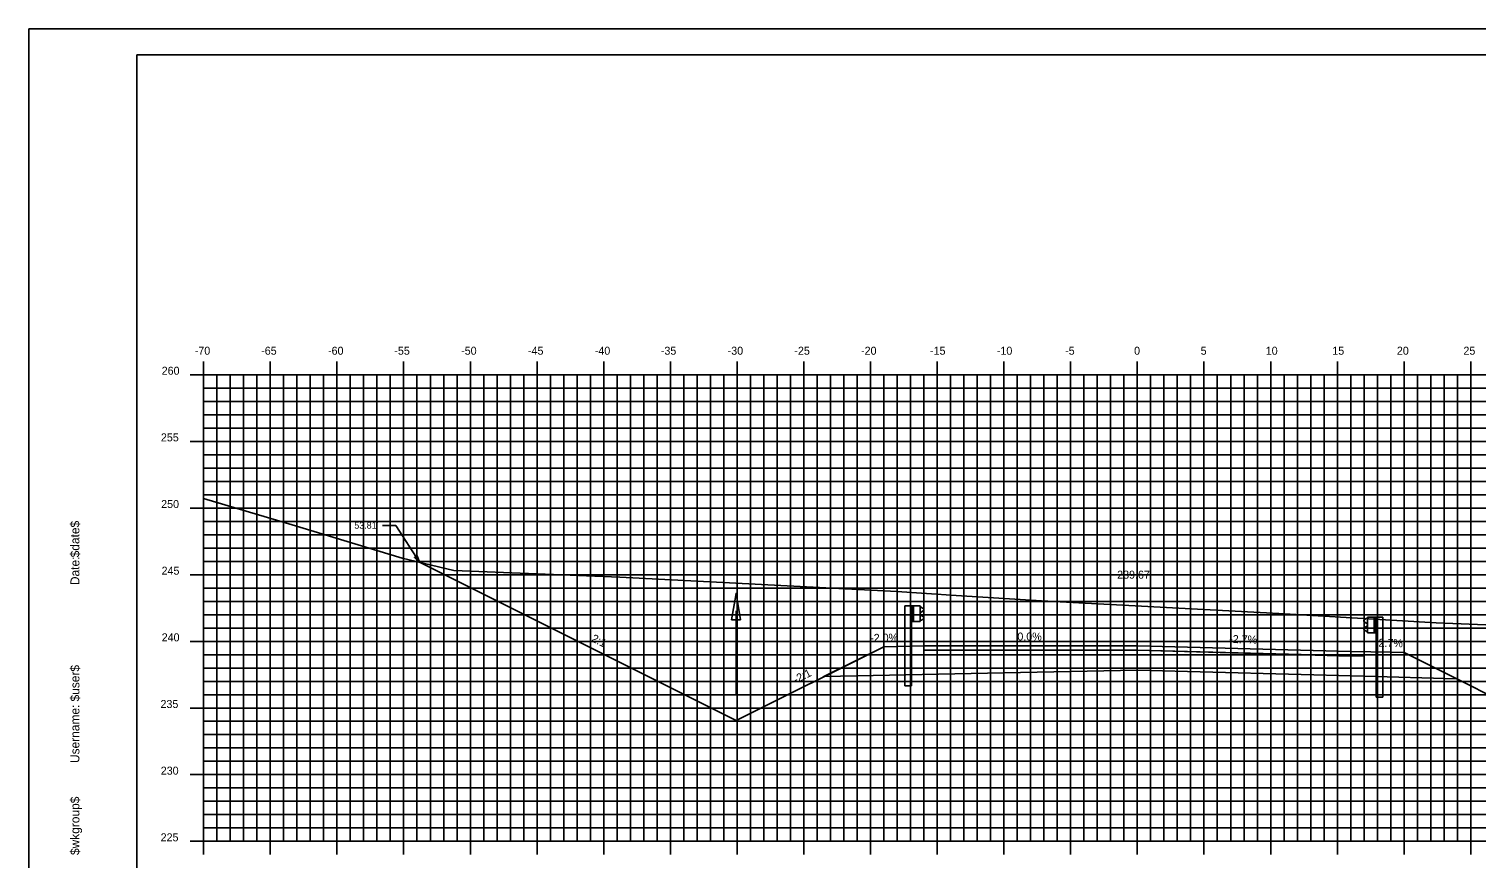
# Model space of a CAD drawing. Extents: x 1160718 to 1173142, y 616002 to 617630.
# Drawn here: x 1168770.5 to 1168879, y 616661.7 to 616723.9 of the extents above; entities that cross this region are included whole.
import ezdxf

# ---------------------------------------------------------------- set-up
doc = ezdxf.new("R2010")
doc.units = 0
for name, color, linetype in [('ANNOTATION', 7, 'Continuous'), ('BORDER', 7, 'Continuous'), ('D_Drainage_Ditch_Line', 7, 'Continuous'), ('D_Guardrail_Beam_Lt', 7, 'Continuous'), ('D_Guardrail_Beam_Rt', 7, 'Continuous'), ('D_Roadway_Centerline', 7, 'Continuous'), ('D_Roadway_Centerline_Text', 7, 'Continuous'), ('D_Roadway_Edge_Shoulder', 7, 'Continuous'), ('D_Roadway_Edge_TW', 7, 'Continuous'), ('D_Roadway_Pavement', 7, 'Continuous'), ('D_Roadway_SlopeLines', 7, 'Continuous'), ('D_Roadway_SubGrade', 7, 'Continuous'), ('H_V ANNOTATION', 7, 'Continuous'), ('MAJOR', 7, 'Continuous'), ('MINOR', 7, 'Continuous'), ('PLOT BOUNDARY', 7, 'Continuous'), ('S_Roadway_Centerline', 7, 'Continuous'), ('SHADING', 7, 'Continuous')]:
    doc.layers.add(name, color=color, linetype=linetype)

msp = doc.modelspace()

# ---------------------------------------------------------------- linework, layer by layer
at = {"layer": 'ANNOTATION'}
for p in [(1168797.02, 616686.63), (1168799.8, 616683.86)]:
    msp.add_line(p, (1168798.02, 616686.63), dxfattribs=at)
msp.add_lwpolyline([(1168799.63, 616684.35), (1168799.8, 616683.86), (1168799.42, 616684.21)], close=True, dxfattribs=at)
at = {"layer": 'BORDER'}
for p, q in [((1168938.61, 616721.93), (1168778.61, 616721.93)), ((1168778.61, 616721.93), (1168778.61, 616616.93))]:
    msp.add_line(p, q, dxfattribs=at)
at = {"layer": 'D_Drainage_Ditch_Line'}
msp.add_line((1168823.53, 616680.21), (1168823.53, 616673.96), dxfattribs=at)
msp.add_lwpolyline([(1168823.86, 616679.55), (1168823.2, 616679.55), (1168823.53, 616681.52)], close=True, dxfattribs=at)
at = {"layer": 'D_Guardrail_Beam_Lt'}
for p, q in [((1168836.18, 616680.59), (1168836.18, 616674.59)), ((1168836.65, 616680.59), (1168836.18, 616680.59)), ((1168837.34, 616680.59), (1168836.65, 616680.59)), ((1168836.65, 616680.59), (1168836.65, 616679.42)), ((1168836.72, 616680.59), (1168836.72, 616679.42)), ((1168836.82, 616680.59), (1168836.82, 616679.42)), ((1168837.34, 616679.42), (1168837.34, 616680.59)), ((1168837.34, 616680.5), (1168837.41, 616680.49)), ((1168837.57, 616680.24), (1168837.38, 616680.1)), ((1168837.43, 616680.48), (1168837.57, 616680.38)), ((1168836.65, 616679.42), (1168837.34, 616679.42)), ((1168836.67, 616674.59), (1168836.67, 616679.42)), ((1168837.34, 616680.04), (1168837.34, 616679.97)), ((1168837.41, 616679.52), (1168837.34, 616679.5)), ((1168837.38, 616679.9), (1168837.57, 616679.77)), ((1168837.57, 616679.62), (1168837.43, 616679.52)), ((1168836.67, 616674.59), (1168836.18, 616674.59))]:
    msp.add_line(p, q, dxfattribs=at)
for centre, major_axis, start_param, end_param in [((1168837.42, 616680.04), (-0.0789, 0), 5.323254, 6.283185), ((1168837.41, 616680.45), (0.0417, 0), 0.959931, 1.376053), ((1168837.52, 616680.31), (0.0877, 0), 5.323254, 7.243116), ((1168837.42, 616679.97), (-0.0789, 0), 6.283185, 7.243116), ((1168837.41, 616679.56), (0.0417, 0), 4.907132, 5.323254), ((1168837.52, 616679.7), (0.0877, 0), 5.323254, 7.243116)]:
    msp.add_ellipse(centre, major_axis=major_axis, ratio=0.995501, start_param=start_param, end_param=end_param, dxfattribs=at)
at = {"layer": 'D_Guardrail_Beam_Rt'}
for p, q in [((1168870.77, 616679.65), (1168870.63, 616679.55)), ((1168870.63, 616679.4), (1168870.82, 616679.27)), ((1168870.82, 616679.07), (1168870.63, 616678.93)), ((1168870.86, 616679.67), (1168870.79, 616679.65)), ((1168870.86, 616679.75), (1168871.55, 616679.75)), ((1168870.86, 616678.58), (1168870.86, 616679.75)), ((1168870.86, 616679.2), (1168870.86, 616679.13)), ((1168871.38, 616679.75), (1168871.38, 616678.58)), ((1168871.49, 616679.75), (1168871.49, 616678.58)), ((1168871.55, 616679.75), (1168872.02, 616679.75)), ((1168871.55, 616679.75), (1168871.55, 616678.58)), ((1168872.02, 616679.75), (1168872.02, 616673.75)), ((1168870.63, 616678.79), (1168870.77, 616678.69)), ((1168870.79, 616678.68), (1168870.86, 616678.67)), ((1168871.55, 616678.58), (1168870.86, 616678.58)), ((1168871.53, 616673.75), (1168871.53, 616678.58)), ((1168871.53, 616673.75), (1168872.02, 616673.75))]:
    msp.add_line(p, q, dxfattribs=at)
for centre, major_axis, start_param, end_param in [((1168870.68, 616679.47), (-0.0877, 0), 5.323254, 7.243116), ((1168870.8, 616679.61), (-0.0417, 0), 4.907132, 5.323254), ((1168870.78, 616679.2), (0.0789, 0), 0, 0.959931), ((1168870.78, 616679.13), (0.0789, 0), 5.323254, 6.283185), ((1168870.68, 616678.86), (-0.0877, 0), 5.323254, 7.243116), ((1168870.8, 616678.72), (-0.0417, 0), 0.959931, 1.376053)]:
    msp.add_ellipse(centre, major_axis=major_axis, ratio=0.995501, start_param=start_param, end_param=end_param, dxfattribs=at)
at = {"layer": 'D_Roadway_Edge_Shoulder'}
msp.add_lwpolyline([(1168837.61, 616677.59), (1168837.61, 616677.26)], dxfattribs=at)
at = {"layer": 'D_Roadway_Edge_TW'}
for p, q in [((1168837.61, 616677.26), (1168837.61, 616677.59)), ((1168837.61, 616677.59), (1168853.61, 616677.59)), ((1168853.61, 616677.26), (1168837.61, 616677.26)), ((1168853.61, 616677.59), (1168869.61, 616677.17)), ((1168869.61, 616676.83), (1168853.61, 616677.26))]:
    msp.add_line(p, q, dxfattribs=at)
at = {"layer": 'D_Roadway_Pavement'}
msp.add_lwpolyline([(1168837.61, 616677.26), (1168837.61, 616677.26), (1168853.61, 616677.26), (1168869.61, 616676.83), (1168869.61, 616676.83), (1168853.61, 616677.26)], close=True, dxfattribs=at)
for points in [[(1168837.61, 616677.26), (1168837.61, 616677.26)], [(1168837.61, 616677.26), (1168837.61, 616677.26)], [(1168869.61, 616676.83), (1168869.61, 616676.83)], [(1168869.61, 616676.83), (1168869.61, 616676.83)]]:
    msp.add_lwpolyline(points, dxfattribs=at)
at = {"layer": 'D_Roadway_SlopeLines'}
for points in [[(1168823.53, 616671.99), (1168799.8, 616683.86)], [(1168834.61, 616677.53), (1168823.53, 616671.99)], [(1168873.61, 616677.09), (1168884.69, 616671.55)]]:
    msp.add_lwpolyline(points, dxfattribs=at)
at = {"layer": 'D_Roadway_SubGrade'}
for p, q in [((1168834.61, 616677.53), (1168830.06, 616675.26)), ((1168837.61, 616677.59), (1168834.61, 616677.53)), ((1168837.61, 616675.44), (1168837.61, 616677.59)), ((1168837.61, 616675.76), (1168837.61, 616677.26)), ((1168837.61, 616677.26), (1168853.61, 616677.26)), ((1168853.61, 616677.26), (1168870.61, 616676.81)), ((1168869.61, 616677.17), (1168872.61, 616677.11)), ((1168870.61, 616675.31), (1168870.61, 616677.15))]:
    msp.add_line(p, q, dxfattribs=at)
msp.add_lwpolyline([(1168869.61, 616677.17), (1168872.61, 616677.11), (1168873.61, 616677.09)], dxfattribs=at)
at = {"layer": 'MAJOR'}
for p, q in [((1168783.61, 616698.93), (1168783.61, 616697.93)), ((1168788.61, 616698.93), (1168788.61, 616697.93)), ((1168793.61, 616698.93), (1168793.61, 616697.93)), ((1168798.61, 616698.93), (1168798.61, 616697.93)), ((1168803.61, 616698.93), (1168803.61, 616697.93)), ((1168808.61, 616698.93), (1168808.61, 616697.93)), ((1168813.61, 616698.93), (1168813.61, 616697.93)), ((1168818.61, 616698.93), (1168818.61, 616697.93)), ((1168823.61, 616698.93), (1168823.61, 616697.93)), ((1168828.61, 616698.93), (1168828.61, 616697.93)), ((1168833.61, 616698.93), (1168833.61, 616697.93)), ((1168838.61, 616698.93), (1168838.61, 616697.93)), ((1168843.61, 616698.93), (1168843.61, 616697.93)), ((1168848.61, 616698.93), (1168848.61, 616697.93)), ((1168853.61, 616698.93), (1168853.61, 616697.93)), ((1168858.61, 616698.93), (1168858.61, 616697.93)), ((1168863.61, 616698.93), (1168863.61, 616697.93)), ((1168868.61, 616698.93), (1168868.61, 616697.93)), ((1168873.61, 616698.93), (1168873.61, 616697.93)), ((1168878.61, 616698.93), (1168878.61, 616697.93)), ((1168782.61, 616697.93), (1168783.61, 616697.93)), ((1168783.61, 616697.93), (1168923.61, 616697.93)), ((1168783.61, 616662.93), (1168783.61, 616697.93)), ((1168783.61, 616662.93), (1168783.61, 616697.93)), ((1168783.61, 616697.93), (1168923.61, 616697.93)), ((1168788.61, 616662.93), (1168788.61, 616697.93)), ((1168793.61, 616662.93), (1168793.61, 616697.93)), ((1168798.61, 616662.93), (1168798.61, 616697.93)), ((1168803.61, 616662.93), (1168803.61, 616697.93)), ((1168808.61, 616662.93), (1168808.61, 616697.93)), ((1168813.61, 616662.93), (1168813.61, 616697.93)), ((1168818.61, 616662.93), (1168818.61, 616697.93)), ((1168823.61, 616662.93), (1168823.61, 616697.93)), ((1168828.61, 616662.93), (1168828.61, 616697.93)), ((1168833.61, 616662.93), (1168833.61, 616697.93)), ((1168838.61, 616662.93), (1168838.61, 616697.93)), ((1168843.61, 616662.93), (1168843.61, 616697.93)), ((1168848.61, 616662.93), (1168848.61, 616697.93)), ((1168853.61, 616662.93), (1168853.61, 616697.93)), ((1168858.61, 616662.93), (1168858.61, 616697.93)), ((1168863.61, 616662.93), (1168863.61, 616697.93)), ((1168868.61, 616662.93), (1168868.61, 616697.93)), ((1168873.61, 616662.93), (1168873.61, 616697.93)), ((1168878.61, 616662.93), (1168878.61, 616697.93)), ((1168782.61, 616692.93), (1168783.61, 616692.93)), ((1168783.61, 616692.93), (1168923.61, 616692.93)), ((1168782.61, 616687.93), (1168783.61, 616687.93)), ((1168783.61, 616687.93), (1168923.61, 616687.93)), ((1168782.61, 616682.93), (1168783.61, 616682.93)), ((1168783.61, 616682.93), (1168923.61, 616682.93)), ((1168782.61, 616677.93), (1168783.61, 616677.93)), ((1168783.61, 616677.93), (1168923.61, 616677.93)), ((1168782.61, 616672.93), (1168783.61, 616672.93)), ((1168783.61, 616672.93), (1168923.61, 616672.93)), ((1168782.61, 616667.93), (1168783.61, 616667.93)), ((1168783.61, 616667.93), (1168923.61, 616667.93)), ((1168782.61, 616662.93), (1168783.61, 616662.93)), ((1168783.61, 616662.93), (1168923.61, 616662.93)), ((1168783.61, 616662.93), (1168923.61, 616662.93)), ((1168783.61, 616661.93), (1168783.61, 616662.93)), ((1168788.61, 616661.93), (1168788.61, 616662.93)), ((1168793.61, 616661.93), (1168793.61, 616662.93)), ((1168798.61, 616661.93), (1168798.61, 616662.93)), ((1168803.61, 616661.93), (1168803.61, 616662.93)), ((1168808.61, 616661.93), (1168808.61, 616662.93)), ((1168813.61, 616661.93), (1168813.61, 616662.93)), ((1168818.61, 616661.93), (1168818.61, 616662.93)), ((1168823.61, 616661.93), (1168823.61, 616662.93)), ((1168828.61, 616661.93), (1168828.61, 616662.93)), ((1168833.61, 616661.93), (1168833.61, 616662.93)), ((1168838.61, 616661.93), (1168838.61, 616662.93)), ((1168843.61, 616661.93), (1168843.61, 616662.93)), ((1168848.61, 616661.93), (1168848.61, 616662.93)), ((1168853.61, 616661.93), (1168853.61, 616662.93)), ((1168858.61, 616661.93), (1168858.61, 616662.93)), ((1168863.61, 616661.93), (1168863.61, 616662.93)), ((1168868.61, 616661.93), (1168868.61, 616662.93)), ((1168873.61, 616661.93), (1168873.61, 616662.93)), ((1168878.61, 616661.93), (1168878.61, 616662.93))]:
    msp.add_line(p, q, dxfattribs=at)
at = {"layer": 'MINOR'}
for p, q in [((1168784.61, 616662.93), (1168784.61, 616697.93)), ((1168785.61, 616662.93), (1168785.61, 616697.93)), ((1168786.61, 616662.93), (1168786.61, 616697.93)), ((1168787.61, 616662.93), (1168787.61, 616697.93)), ((1168789.61, 616662.93), (1168789.61, 616697.93)), ((1168790.61, 616662.93), (1168790.61, 616697.93)), ((1168791.61, 616662.93), (1168791.61, 616697.93)), ((1168792.61, 616662.93), (1168792.61, 616697.93)), ((1168794.61, 616662.93), (1168794.61, 616697.93)), ((1168795.61, 616662.93), (1168795.61, 616697.93)), ((1168796.61, 616662.93), (1168796.61, 616697.93)), ((1168797.61, 616662.93), (1168797.61, 616697.93)), ((1168799.61, 616662.93), (1168799.61, 616697.93)), ((1168800.61, 616662.93), (1168800.61, 616697.93)), ((1168801.61, 616662.93), (1168801.61, 616697.93)), ((1168802.61, 616662.93), (1168802.61, 616697.93)), ((1168804.61, 616662.93), (1168804.61, 616697.93)), ((1168805.61, 616662.93), (1168805.61, 616697.93)), ((1168806.61, 616662.93), (1168806.61, 616697.93)), ((1168807.61, 616662.93), (1168807.61, 616697.93)), ((1168809.61, 616662.93), (1168809.61, 616697.93)), ((1168810.61, 616662.93), (1168810.61, 616697.93)), ((1168811.61, 616662.93), (1168811.61, 616697.93)), ((1168812.61, 616662.93), (1168812.61, 616697.93)), ((1168814.61, 616662.93), (1168814.61, 616697.93)), ((1168815.61, 616662.93), (1168815.61, 616697.93)), ((1168816.61, 616662.93), (1168816.61, 616697.93)), ((1168817.61, 616662.93), (1168817.61, 616697.93)), ((1168819.61, 616662.93), (1168819.61, 616697.93)), ((1168820.61, 616662.93), (1168820.61, 616697.93)), ((1168821.61, 616662.93), (1168821.61, 616697.93)), ((1168822.61, 616662.93), (1168822.61, 616697.93)), ((1168824.61, 616662.93), (1168824.61, 616697.93)), ((1168825.61, 616662.93), (1168825.61, 616697.93)), ((1168826.61, 616662.93), (1168826.61, 616697.93)), ((1168827.61, 616662.93), (1168827.61, 616697.93)), ((1168829.61, 616662.93), (1168829.61, 616697.93)), ((1168830.61, 616662.93), (1168830.61, 616697.93)), ((1168831.61, 616662.93), (1168831.61, 616697.93)), ((1168832.61, 616662.93), (1168832.61, 616697.93)), ((1168834.61, 616662.93), (1168834.61, 616697.93)), ((1168835.61, 616662.93), (1168835.61, 616697.93)), ((1168836.61, 616662.93), (1168836.61, 616697.93)), ((1168837.61, 616662.93), (1168837.61, 616697.93)), ((1168839.61, 616662.93), (1168839.61, 616697.93)), ((1168840.61, 616662.93), (1168840.61, 616697.93)), ((1168841.61, 616662.93), (1168841.61, 616697.93)), ((1168842.61, 616662.93), (1168842.61, 616697.93)), ((1168844.61, 616662.93), (1168844.61, 616697.93)), ((1168845.61, 616662.93), (1168845.61, 616697.93)), ((1168846.61, 616662.93), (1168846.61, 616697.93)), ((1168847.61, 616662.93), (1168847.61, 616697.93)), ((1168849.61, 616662.93), (1168849.61, 616697.93)), ((1168850.61, 616662.93), (1168850.61, 616697.93)), ((1168851.61, 616662.93), (1168851.61, 616697.93)), ((1168852.61, 616662.93), (1168852.61, 616697.93)), ((1168854.61, 616662.93), (1168854.61, 616697.93)), ((1168855.61, 616662.93), (1168855.61, 616697.93)), ((1168856.61, 616662.93), (1168856.61, 616697.93)), ((1168857.61, 616662.93), (1168857.61, 616697.93)), ((1168859.61, 616662.93), (1168859.61, 616697.93)), ((1168860.61, 616662.93), (1168860.61, 616697.93)), ((1168861.61, 616662.93), (1168861.61, 616697.93)), ((1168862.61, 616662.93), (1168862.61, 616697.93)), ((1168864.61, 616662.93), (1168864.61, 616697.93)), ((1168865.61, 616662.93), (1168865.61, 616697.93)), ((1168866.61, 616662.93), (1168866.61, 616697.93)), ((1168867.61, 616662.93), (1168867.61, 616697.93)), ((1168869.61, 616662.93), (1168869.61, 616697.93)), ((1168870.61, 616662.93), (1168870.61, 616697.93)), ((1168871.61, 616662.93), (1168871.61, 616697.93)), ((1168872.61, 616662.93), (1168872.61, 616697.93)), ((1168874.61, 616662.93), (1168874.61, 616697.93)), ((1168875.61, 616662.93), (1168875.61, 616697.93)), ((1168876.61, 616662.93), (1168876.61, 616697.93)), ((1168877.61, 616662.93), (1168877.61, 616697.93)), ((1168783.61, 616696.93), (1168923.61, 616696.93)), ((1168783.61, 616696.93), (1168784.61, 616696.93)), ((1168783.61, 616695.93), (1168923.61, 616695.93)), ((1168783.61, 616695.93), (1168784.61, 616695.93)), ((1168783.61, 616694.93), (1168923.61, 616694.93)), ((1168783.61, 616694.93), (1168784.61, 616694.93)), ((1168783.61, 616693.93), (1168923.61, 616693.93)), ((1168783.61, 616693.93), (1168784.61, 616693.93)), ((1168783.61, 616691.93), (1168923.61, 616691.93)), ((1168783.61, 616691.93), (1168784.61, 616691.93)), ((1168783.61, 616690.93), (1168923.61, 616690.93)), ((1168783.61, 616690.93), (1168784.61, 616690.93)), ((1168783.61, 616689.93), (1168923.61, 616689.93)), ((1168783.61, 616689.93), (1168784.61, 616689.93)), ((1168783.61, 616688.93), (1168923.61, 616688.93)), ((1168783.61, 616688.93), (1168784.61, 616688.93)), ((1168783.61, 616686.93), (1168923.61, 616686.93)), ((1168783.61, 616686.93), (1168784.61, 616686.93)), ((1168783.61, 616685.93), (1168923.61, 616685.93)), ((1168783.61, 616685.93), (1168784.61, 616685.93)), ((1168783.61, 616684.93), (1168923.61, 616684.93)), ((1168783.61, 616684.93), (1168784.61, 616684.93)), ((1168783.61, 616683.93), (1168923.61, 616683.93)), ((1168783.61, 616683.93), (1168784.61, 616683.93)), ((1168783.61, 616681.93), (1168923.61, 616681.93)), ((1168783.61, 616681.93), (1168784.61, 616681.93)), ((1168783.61, 616680.93), (1168923.61, 616680.93)), ((1168783.61, 616680.93), (1168784.61, 616680.93)), ((1168783.61, 616679.93), (1168923.61, 616679.93)), ((1168783.61, 616679.93), (1168784.61, 616679.93)), ((1168783.61, 616678.93), (1168923.61, 616678.93)), ((1168783.61, 616678.93), (1168784.61, 616678.93)), ((1168783.61, 616676.93), (1168923.61, 616676.93)), ((1168783.61, 616676.93), (1168784.61, 616676.93)), ((1168783.61, 616675.93), (1168923.61, 616675.93)), ((1168783.61, 616675.93), (1168784.61, 616675.93)), ((1168783.61, 616674.93), (1168923.61, 616674.93)), ((1168783.61, 616674.93), (1168784.61, 616674.93)), ((1168783.61, 616673.93), (1168923.61, 616673.93)), ((1168783.61, 616673.93), (1168784.61, 616673.93)), ((1168783.61, 616671.93), (1168923.61, 616671.93)), ((1168783.61, 616671.93), (1168784.61, 616671.93)), ((1168783.61, 616670.93), (1168923.61, 616670.93)), ((1168783.61, 616670.93), (1168784.61, 616670.93)), ((1168783.61, 616669.93), (1168923.61, 616669.93)), ((1168783.61, 616669.93), (1168784.61, 616669.93)), ((1168783.61, 616668.93), (1168923.61, 616668.93)), ((1168783.61, 616668.93), (1168784.61, 616668.93)), ((1168783.61, 616666.93), (1168923.61, 616666.93)), ((1168783.61, 616666.93), (1168784.61, 616666.93)), ((1168783.61, 616665.93), (1168923.61, 616665.93)), ((1168783.61, 616665.93), (1168784.61, 616665.93)), ((1168783.61, 616664.93), (1168923.61, 616664.93)), ((1168783.61, 616664.93), (1168784.61, 616664.93)), ((1168783.61, 616663.93), (1168923.61, 616663.93)), ((1168783.61, 616663.93), (1168784.61, 616663.93))]:
    msp.add_line(p, q, dxfattribs=at)
at = {"layer": 'PLOT BOUNDARY'}
msp.add_lwpolyline([(1168770.52, 616613.87), (1168940.52, 616613.87), (1168940.52, 616723.87), (1168770.52, 616723.87)], close=True, dxfattribs=at)
at = {"layer": 'S_Roadway_Centerline'}
msp.add_lwpolyline([(1168783.61, 616688.64), (1168789.99, 616686.74), (1168798.51, 616684.16), (1168802.37, 616683.25), (1168814.81, 616682.74), (1168835.58, 616681.67), (1168840.03, 616681.37), (1168846.43, 616680.96), (1168864.23, 616680.01), (1168876.02, 616679.31), (1168884.08, 616678.99), (1168896.43, 616677.95), (1168901.07, 616677.79), (1168910.6, 616676.38), (1168913.22, 616676.11), (1168923.61, 616679.62)], dxfattribs=at)
at = {"layer": 'SHADING'}
for points in [[(1168853.61, 616675.76), (1168843.61, 616675.56), (1168830.13, 616675.29)], [(1168853.61, 616675.76), (1168870.61, 616675.31), (1168877.54, 616675.12)]]:
    msp.add_lwpolyline(points, dxfattribs=at)

# ---------------------------------------------------------------- texts
at = {"layer": 'ANNOTATION'}
msp.add_text("53.81'", height=0.5, dxfattribs=at).set_placement((1168794.91, 616686.38))
for s, rotation, p in [('2:1', 333.4349, (1168812.63, 616677.96)), ('-2.0%', 1.1458, (1168833.59, 616677.88)), ('0.0%', 360, (1168844.62, 616677.99)), ('-2.7%', 358.4725, (1168860.49, 616677.81)), ('-2.7%', 358.8542, (1168871.42, 616677.53)), ('-2:1', 26.5651, (1168828, 616674.75))]:
    msp.add_text(s, height=0.6, rotation=rotation, dxfattribs=at).set_placement(p)
at = {"layer": 'BORDER'}
for s, p in [('$date$', (1168774.3, 616684.23)), ('Date:', (1168774.3, 616682.15)), ('$user$', (1168774.3, 616673.42)), ('Username:', (1168774.3, 616668.8)), ('$wkgroup$', (1168774.3, 616661.9))]:
    msp.add_text(s, height=0.67, rotation=90, dxfattribs=at).set_placement(p)
at = {"layer": 'D_Roadway_Centerline'}
for s in ['C', 'L']:
    msp.add_text(s, height=0.0146, dxfattribs=at).set_placement((1168853.61, 616677.59))
at = {"layer": 'D_Roadway_Centerline_Text'}
msp.add_text('239.67', height=0.6, dxfattribs=at).set_placement((1168852.1, 616682.63))
at = {"layer": 'H_V ANNOTATION'}
for s, p in [('-70', (1168782.95, 616699.43)), ('-65', (1168787.93, 616699.43)), ('-60', (1168792.94, 616699.43)), ('-55', (1168797.91, 616699.43)), ('-50', (1168802.92, 616699.43)), ('-45', (1168807.93, 616699.43)), ('-40', (1168812.94, 616699.43)), ('-35', (1168817.89, 616699.43)), ('-30', (1168822.9, 616699.43)), ('-25', (1168827.9, 616699.43)), ('-20', (1168832.9, 616699.43)), ('-15', (1168838.07, 616699.43)), ('-10', (1168843.08, 616699.43)), ('-5', (1168848.2, 616699.43)), ('0', (1168853.37, 616699.43)), ('5', (1168858.36, 616699.43)), ('10', (1168863.24, 616699.43)), ('15', (1168868.23, 616699.43)), ('20', (1168873.07, 616699.43)), ('25', (1168878.06, 616699.43)), ('260', (1168780.47, 616697.93)), ('255', (1168780.41, 616692.93)), ('250', (1168780.43, 616687.93)), ('245', (1168780.46, 616682.93)), ('240', (1168780.47, 616677.93)), ('235', (1168780.38, 616672.93)), ('230', (1168780.4, 616667.93)), ('225', (1168780.39, 616662.93))]:
    msp.add_text(s, height=0.6, dxfattribs=at).set_placement(p)

doc.saveas('drawing.dxf')
